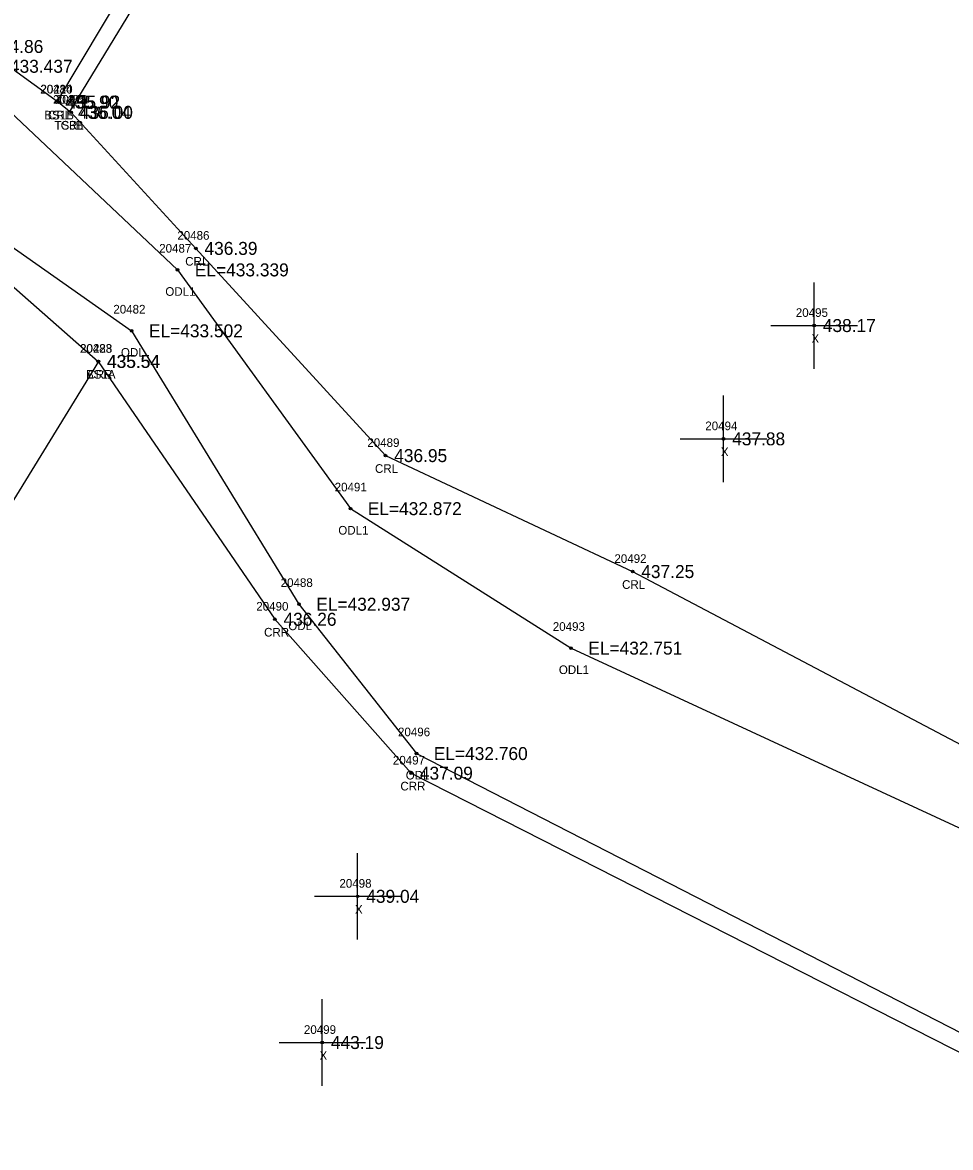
# Model space of a CAD drawing. Extents: x 1763022 to 1764007, y 824123 to 825394.
# Drawn here: x 1763501.5 to 1763608.9, y 824685.4 to 824815.6 of the extents above; entities that cross this region are included whole.
import ezdxf

# ---------------------------------------------------------------- set-up
doc = ezdxf.new("R2010")
doc.units = 0
for name, color, linetype in [('RD_DTM_BkLn2', 7, 'Continuous'), ('RD_DTM_BkLn_txCode', 7, 'Continuous'), ('RD_EX_H2O', 7, 'Continuous'), ('RD_EX_H2O_txCode', 7, 'Continuous'), ('RD_EX_Misc', 7, 'Continuous'), ('RD_EX_Misc_txCode', 7, 'Continuous'), ('RD_EX_TX_H2O_ELEV', 7, 'Continuous'), ('RD_EX_TX_Misc_ELEV', 7, 'Continuous'), ('RD_SMD_Locator', 7, 'Continuous')]:
    doc.layers.add(name, color=color, linetype=linetype)

msp = doc.modelspace()

# ---------------------------------------------------------------- linework, layer by layer
at = {"layer": 'RD_DTM_BkLn2'}
for points in [[(1763571.6, 824910.75), (1763575.51, 824907.86), (1763568.82, 824899.15), (1763539.31, 824858.47), (1763506.93, 824805.24)], [(1763572.81, 824907.86), (1763567.31, 824900.56), (1763537.52, 824860.02), (1763505.47, 824806.41)], [(1763510.31, 824776.41), (1763487.73, 824739.69), (1763467.72, 824746.4), (1763457.88, 824742.49), (1763448.32, 824732.5), (1763429.76, 824699.16), (1763407.64, 824655.12), (1763386.68, 824612.12), (1763370.96, 824575.87)]]:
    msp.add_lwpolyline(points, dxfattribs=at)
at = {"layer": 'RD_EX_H2O'}
for points in [[(1763496.79, 824812.85), (1763505.69, 824806.42), (1763507.16, 824805.23), (1763521.58, 824789.49), (1763543.54, 824765.51), (1763572.14, 824752.09), (1763662.42, 824704.48), (1763697.56, 824670.47), (1763707.93, 824630.76), (1763723.52, 824595.87), (1763766.82, 824582.67), (1763818.29, 824585.49), (1763920.08, 824604.11)], [(1763494.44, 824810.56), (1763519.46, 824787), (1763539.48, 824759.37), (1763565.01, 824743.23), (1763659.79, 824699.35), (1763693.94, 824667), (1763705.55, 824629.75), (1763723.44, 824593.51), (1763767.2, 824575.02), (1763820.02, 824582.79), (1763920.83, 824600.99)], [(1763486.08, 824799.65), (1763514.15, 824779.95), (1763533.52, 824748.31), (1763547.12, 824731.03), (1763648.42, 824679.07), (1763662.67, 824682.83), (1763683.5, 824662.48), (1763694.46, 824627.33), (1763694.82, 824601.41), (1763712.85, 824586.53), (1763766.86, 824564.42), (1763816.87, 824572.85), (1763926.33, 824585.82)], [(1763485.59, 824798.12), (1763510.28, 824776.41), (1763530.73, 824746.57), (1763546.51, 824728.76), (1763647.95, 824677.16), (1763661.46, 824680.21), (1763679.15, 824659.29), (1763688.38, 824626.34), (1763689.04, 824599.45), (1763710.73, 824574.27), (1763740.3, 824562), (1763762.69, 824555.26), (1763820.3, 824563.65), (1763926.69, 824582.3)]]:
    msp.add_lwpolyline(points, dxfattribs=at)
at = {"layer": 'RD_EX_Misc'}
for p, q in [((1763593.15, 824775.56), (1763593.15, 824785.56)), ((1763588.15, 824780.56), (1763598.15, 824780.56)), ((1763582.66, 824762.45), (1763582.66, 824772.45)), ((1763577.66, 824767.45), (1763587.66, 824767.45)), ((1763540.31, 824709.51), (1763540.31, 824719.51)), ((1763535.31, 824714.51), (1763545.31, 824714.51)), ((1763536.21, 824692.59), (1763536.21, 824702.59)), ((1763531.21, 824697.59), (1763541.21, 824697.59))]:
    msp.add_line(p, q, dxfattribs=at)
at = {"layer": 'RD_SMD_Locator'}
for centre in [(1763505.47, 824806.41), (1763505.69, 824806.42), (1763506.93, 824805.24), (1763507.16, 824805.23), (1763521.58, 824789.49), (1763519.46, 824787), (1763514.15, 824779.95), (1763593.15, 824780.56), (1763510.28, 824776.41), (1763510.31, 824776.41), (1763582.66, 824767.45), (1763543.54, 824765.51), (1763539.48, 824759.37), (1763572.14, 824752.09), (1763533.52, 824748.31), (1763530.73, 824746.57), (1763565.01, 824743.23), (1763547.12, 824731.03), (1763546.51, 824728.76), (1763540.31, 824714.51), (1763536.21, 824697.59)]:
    msp.add_circle(centre, 0.15, dxfattribs=at)

# ---------------------------------------------------------------- texts
at = {"layer": 'RD_DTM_BkLn_txCode'}
for s, p in [('20210', (1763503.6, 824807.41)), ('20211', (1763505.38, 824806.24)), ('BS1B', (1763504.05, 824804.41)), ('TS3B', (1763505.22, 824803.24)), ('20228', (1763508.19, 824777.41)), ('BS1A', (1763508.87, 824774.41))]:
    msp.add_text(s, height=1, dxfattribs=at).set_placement(p)
at = {"layer": 'RD_EX_H2O_txCode'}
for s, p in [('20484', (1763503.57, 824807.42)), ('20485', (1763505.05, 824806.23)), ('CRL', (1763504.46, 824804.42)), ('CRL', (1763505.94, 824803.23)), ('20486', (1763519.44, 824790.49)), ('20487', (1763517.34, 824789)), ('CRL', (1763520.35, 824787.49)), ('ODL1', (1763518.05, 824784)), ('20482', (1763512.03, 824781.95)), ('20483', (1763508.16, 824777.41)), ('ODL', (1763512.91, 824776.95)), ('CRR', (1763509.03, 824774.41)), ('20489', (1763541.43, 824766.51)), ('CRL', (1763542.32, 824763.51)), ('20491', (1763537.65, 824761.37)), ('ODL1', (1763538.07, 824756.37)), ('20492', (1763570.03, 824753.09)), ('20488', (1763531.4, 824750.31)), ('CRL', (1763570.92, 824750.09)), ('20490', (1763528.58, 824747.57)), ('ODL', (1763532.28, 824745.31)), ('20493', (1763562.9, 824745.23)), ('CRR', (1763529.48, 824744.57)), ('ODL1', (1763563.6, 824740.23)), ('20496', (1763544.98, 824733.03)), ('20497', (1763544.39, 824729.76)), ('ODL', (1763545.88, 824728.03)), ('CRR', (1763545.26, 824726.76))]:
    msp.add_text(s, height=1, dxfattribs=at).set_placement(p)
at = {"layer": 'RD_EX_Misc_txCode'}
for s, p in [('20495', (1763591.03, 824781.56)), ('X', (1763592.84, 824778.56)), ('20494', (1763580.55, 824768.45)), ('X', (1763582.35, 824765.45)), ('20498', (1763538.2, 824715.51)), ('X', (1763540, 824712.51)), ('20499', (1763534.09, 824698.59)), ('X', (1763535.9, 824695.59))]:
    msp.add_text(s, height=1, dxfattribs=at).set_placement(p)
at = {"layer": 'RD_EX_TX_H2O_ELEV'}
for s, p in [('434.86', (1763497.79, 824812.1)), ('EL=433.437', (1763496.44, 824809.81)), ('435.92', (1763506.69, 824805.67)), ('436.00', (1763508.16, 824804.48)), ('436.39', (1763522.58, 824788.74)), ('EL=433.339', (1763521.46, 824786.25)), ('EL=433.502', (1763516.15, 824779.2)), ('435.54', (1763511.28, 824775.66)), ('436.95', (1763544.54, 824764.76)), ('EL=432.872', (1763541.48, 824758.62)), ('437.25', (1763573.14, 824751.34)), ('EL=432.937', (1763535.52, 824747.56)), ('436.26', (1763531.73, 824745.82)), ('EL=432.751', (1763567.01, 824742.48)), ('EL=432.760', (1763549.12, 824730.28)), ('437.09', (1763547.51, 824728.01))]:
    msp.add_text(s, height=1.5, dxfattribs=at).set_placement(p)
at = {"layer": 'RD_EX_TX_Misc_ELEV'}
for s, p in [('435.90', (1763506.47, 824805.66)), ('436.04', (1763507.93, 824804.49)), ('438.17', (1763594.15, 824779.81)), ('435.54', (1763511.31, 824775.66)), ('437.88', (1763583.66, 824766.7)), ('439.04', (1763541.31, 824713.76)), ('443.19', (1763537.21, 824696.84))]:
    msp.add_text(s, height=1.5, dxfattribs=at).set_placement(p)

doc.saveas('drawing.dxf')
